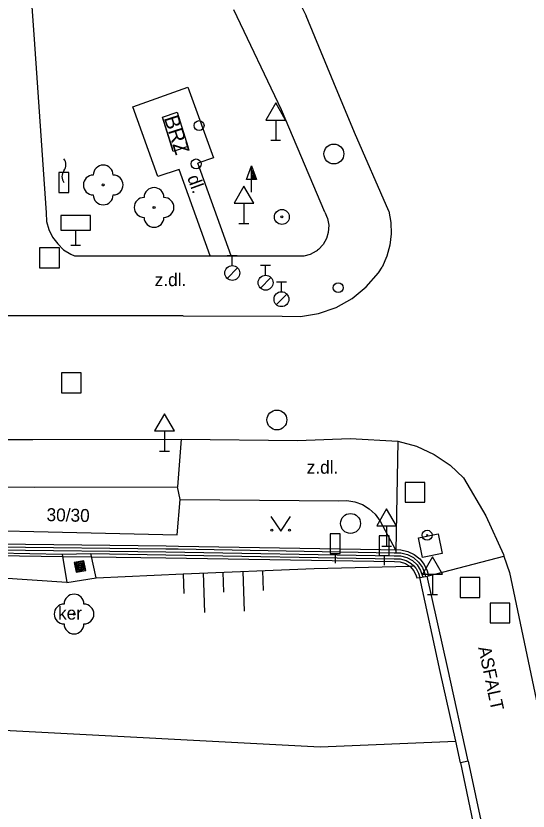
# Model space of a CAD drawing. Extents: x -538441 to -536770, y -1181008 to -1179809.
# Drawn here: x -537827.88 to -537802.07, y -1180541.89 to -1180501.86 of the extents above; entities that cross this region are included whole.
import ezdxf

# ---------------------------------------------------------------- set-up
doc = ezdxf.new("R2010")
doc.units = 0
for name, color, linetype in [('Vrstva 10', 7, 'Continuous'), ('Vrstva 11', 7, 'Continuous'), ('Vrstva 14', 7, 'Continuous'), ('Vrstva 15', 7, 'Continuous'), ('Vrstva 21', 7, 'Continuous'), ('Vrstva 22', 7, 'Continuous'), ('Vrstva 24', 7, 'Continuous'), ('Vrstva 25', 7, 'Continuous'), ('Vrstva 26', 7, 'Continuous'), ('Vrstva 27', 7, 'Continuous'), ('Vrstva 28', 7, 'Continuous'), ('Vrstva 31', 7, 'Continuous'), ('Vrstva 34', 7, 'Continuous'), ('Vrstva 36', 7, 'Continuous'), ('Vrstva 38', 7, 'Continuous'), ('Vrstva 40', 7, 'Continuous'), ('Vrstva 41', 7, 'Continuous'), ('Vrstva 5', 7, 'Continuous'), ('Vrstva 57', 7, 'Continuous'), ('Vrstva 6', 7, 'Continuous'), ('Vrstva 7', 7, 'Continuous'), ('Vrstva 9', 7, 'Continuous')]:
    doc.layers.add(name, color=color, linetype=linetype)

msp = doc.modelspace()

# ---------------------------------------------------------------- linework, layer by layer
at = {"layer": 'Vrstva 10'}
for p, q in [((-537809.09, -1180511.69), (-537810.82, -1180507.735)), ((-537819.46, -1180516.95), (-537839.53, -1180516.98)), ((-537819.46, -1180516.95), (-537814.47, -1180516.98)), ((-537835.714, -1180523.17), (-537827.03, -1180523.18)), ((-537827.03, -1180523.18), (-537819.56, -1180523.17)), ((-537819.56, -1180523.17), (-537813.69, -1180523.23)), ((-537803.01, -1180529.88), (-537801.459, -1180537.207))]:
    msp.add_line(p, q, dxfattribs=at)
for points in [[(-537815.804, -1180496.755), (-537814.527, -1180499.308), (-537814.265, -1180499.831), (-537813.25, -1180501.86)], [(-537810.82, -1180507.735), (-537811.857, -1180505.228), (-537813.25, -1180501.86)], [(-537809.09, -1180511.69), (-537808.995, -1180512.254), (-537808.979, -1180512.826), (-537809.043, -1180513.394), (-537809.185, -1180513.948), (-537809.42, -1180514.51)], [(-537814.47, -1180516.98), (-537813.544, -1180516.988), (-537812.629, -1180516.838), (-537811.75, -1180516.53), (-537810.945, -1180516.081), (-537810.226, -1180515.497), (-537809.617, -1180514.799), (-537809.42, -1180514.51)], [(-537813.69, -1180523.23), (-537811.045, -1180523.141), (-537808.63, -1180523.27)], [(-537808.63, -1180523.27), (-537807.692, -1180523.525), (-537806.808, -1180523.931), (-537806.003, -1180524.476), (-537805.32, -1180525.12)], [(-537805.32, -1180525.12), (-537804.203, -1180527.018), (-537803.32, -1180528.97)], [(-537803.32, -1180528.97), (-537803.291, -1180529.055), (-537803.01, -1180529.88)]]:
    msp.add_lwpolyline(points, dxfattribs=at)
at = {"layer": 'Vrstva 11'}
for p, q in [((-537827.67, -1180492.82), (-537826.98, -1180502.8)), ((-537814.496, -1180506.595), (-537816.902, -1180501.549)), ((-537826.98, -1180502.8), (-537826.36, -1180511.78)), ((-537812.31, -1180511.74), (-537814.496, -1180506.595)), ((-537817.03, -1180513.94), (-537818.72, -1180509.28)), ((-537808.63, -1180523.27), (-537808.73, -1180528.78)), ((-537835.7, -1180525.464), (-537826.94, -1180525.59)), ((-537826.94, -1180525.59), (-537819.73, -1180525.56)), ((-537819.6, -1180526.21), (-537811.61, -1180526.27)), ((-537831.949, -1180528.393), (-537820.316, -1180528.534)), ((-537820.316, -1180528.534), (-537819.693, -1180528.545)), ((-537819.693, -1180528.545), (-537808.486, -1180528.736)), ((-537831.953, -1180528.993), (-537825.505, -1180529.071)), ((-537808.73, -1180528.78), (-537808.732, -1180528.884)), ((-537820.324, -1180529.134), (-537808.797, -1180529.332)), ((-537807.683, -1180530.155), (-537807.535, -1180530.128)), ((-537807.24, -1180530.075), (-537807.158, -1180530.06)), ((-537805.09, -1180539.37), (-537805.48, -1180539.457))]:
    msp.add_line(p, q, dxfattribs=at)
for points in [[(-537821.99, -1180506.44), (-537819.21, -1180505.44), (-537817.93, -1180509.01), (-537818.72, -1180509.28)], [(-537818.09, -1180513.94), (-537819.66, -1180509.59), (-537820.73, -1180509.95), (-537821.99, -1180506.44)], [(-537826.36, -1180511.78), (-537826.33, -1180512.203), (-537826.222, -1180512.614), (-537826.039, -1180512.997), (-537825.77, -1180513.34), (-537825.476, -1180513.627), (-537825.116, -1180513.853), (-537824.92, -1180513.94)], [(-537812.31, -1180511.74), (-537812.174, -1180512.057), (-537812.114, -1180512.396), (-537812.14, -1180512.77), (-537812.233, -1180513.07), (-537812.405, -1180513.369), (-537812.641, -1180513.62), (-537812.69, -1180513.66)], [(-537813.7, -1180513.94), (-537813.362, -1180513.935), (-537813.034, -1180513.851), (-537812.735, -1180513.693), (-537812.69, -1180513.66)], [(-537824.92, -1180513.94), (-537818.09, -1180513.94)], [(-537818.09, -1180513.94), (-537817.03, -1180513.94), (-537813.7, -1180513.94)], [(-537819.56, -1180523.17), (-537819.73, -1180525.56)], [(-537843.21, -1180525.31), (-537843.23, -1180527.47), (-537835.65, -1180527.61), (-537819.75, -1180527.99)], [(-537819.6, -1180526.21), (-537819.73, -1180525.56)], [(-537819.75, -1180527.99), (-537819.6, -1180526.21)], [(-537811.61, -1180526.27), (-537811.203, -1180526.254), (-537810.802, -1180526.318), (-537810.42, -1180526.46), (-537810.074, -1180526.673), (-537809.775, -1180526.949), (-537809.53, -1180527.29)], [(-537809.53, -1180527.29), (-537808.754, -1180528.736), (-537808.73, -1180528.78)], [(-537808.486, -1180528.736), (-537808.138, -1180528.818), (-537807.815, -1180528.975), (-537807.536, -1180529.199), (-537807.313, -1180529.479), (-537807.157, -1180529.802), (-537807.093, -1180530.043)], [(-537825.505, -1180529.071), (-537824.081, -1180529.088)], [(-537824.081, -1180529.088), (-537820.324, -1180529.134)], [(-537808.797, -1180529.332), (-537808.514, -1180529.338), (-537808.243, -1180529.423), (-537808.044, -1180529.555), (-537808.007, -1180529.579), (-537807.823, -1180529.795), (-537807.707, -1180530.054), (-537807.683, -1180530.155)], [(-537807.158, -1180530.06), (-537807.093, -1180530.043), (-537803.291, -1180529.055)], [(-537805.48, -1180539.457), (-537805.72, -1180538.375), (-537806.502, -1180534.855), (-537807.535, -1180530.128)], [(-537805.09, -1180539.37), (-537806.125, -1180534.71), (-537807.158, -1180530.06)]]:
    msp.add_lwpolyline(points, dxfattribs=at)
at = {"layer": 'Vrstva 14'}
for p, q in [((-537819.45, -1180529.941), (-537812.85, -1180529.68)), ((-537825.32, -1180530.39), (-537830.036, -1180530.052)), ((-537823.84, -1180530.14), (-537819.45, -1180529.941)), ((-537843.69, -1180537.02), (-537812.55, -1180538.66)), ((-537812.55, -1180538.66), (-537805.72, -1180538.375))]:
    msp.add_line(p, q, dxfattribs=at)
msp.add_lwpolyline([(-537812.85, -1180529.68), (-537808.044, -1180529.555), (-537807.824, -1180529.549)], dxfattribs=at)
at = {"layer": 'Vrstva 15'}
for p, q in [((-537815.454, -1180529.783), (-537815.414, -1180530.782)), ((-537819.45, -1180529.941), (-537819.411, -1180530.94)), ((-537818.451, -1180529.902), (-537818.372, -1180531.9)), ((-537817.452, -1180529.862), (-537817.412, -1180530.861)), ((-537816.453, -1180529.822), (-537816.374, -1180531.821))]:
    msp.add_line(p, q, dxfattribs=at)
at = {"layer": 'Vrstva 21'}
for radius in [0.375, 0.05]:
    msp.add_circle((-537814.48, -1180511.98), radius, dxfattribs=at)
at = {"layer": 'Vrstva 22'}
for centre in [(-537823.48, -1180510.37), (-537820.92, -1180511.5), (-537824.95, -1180531.97)]:
    msp.add_circle(centre, 0.05, dxfattribs=at)
for centre, start, end in [((-537823.48, -1180509.87), 0, 180), ((-537823.98, -1180510.37), 90, 270), ((-537822.98, -1180510.37), 270, 90), ((-537820.92, -1180511), 0, 180), ((-537823.48, -1180510.87), 180, 0), ((-537821.42, -1180511.5), 90, 270), ((-537820.42, -1180511.5), 270, 90), ((-537820.92, -1180512), 180, 0), ((-537824.95, -1180531.47), 0, 180), ((-537825.45, -1180531.97), 90, 270), ((-537824.45, -1180531.97), 270, 90), ((-537824.95, -1180532.47), 180, 0)]:
    msp.add_arc(centre, 0.5, start, end, dxfattribs=at)
at = {"layer": 'Vrstva 24'}
msp.add_lwpolyline([(-537825.21, -1180510.75), (-537825.21, -1180509.75), (-537825.71, -1180509.75), (-537825.71, -1180510.75)], close=True, dxfattribs=at)
for centre, start, end in [((-537825.86, -1180509.35), 323.1301, 36.8699), ((-537825.06, -1180509.95), 143.1301, 216.8699)]:
    msp.add_arc(centre, 0.5, start, end, dxfattribs=at)
at = {"layer": 'Vrstva 25'}
for p, q in [((-537816.262, -1180510.088), (-537816.01, -1180509.414)), ((-537816.01, -1180510.088), (-537816.262, -1180510.088)), ((-537816.01, -1180510.74), (-537816.01, -1180510.09))]:
    msp.add_line(p, q, dxfattribs=at)
for points in [[(-537815.76, -1180510.09), (-537816.01, -1180510.09), (-537816.01, -1180509.414), (-537816.01, -1180509.414)], [(-537815.817, -1180510.05), (-537815.97, -1180510.05), (-537815.97, -1180509.637)], [(-537815.875, -1180510.01), (-537815.93, -1180510.01), (-537815.93, -1180509.861)], [(-537824.849, -1180529.868), (-537824.358, -1180529.775), (-537824.451, -1180529.284), (-537824.942, -1180529.377)], [(-537824.809, -1180529.81), (-537824.416, -1180529.735), (-537824.491, -1180529.342), (-537824.884, -1180529.417)], [(-537824.77, -1180529.752), (-537824.475, -1180529.696), (-537824.531, -1180529.401), (-537824.826, -1180529.457)], [(-537824.73, -1180529.693), (-537824.533, -1180529.656), (-537824.571, -1180529.459), (-537824.767, -1180529.497)], [(-537824.69, -1180529.635), (-537824.592, -1180529.616), (-537824.61, -1180529.518), (-537824.709, -1180529.536)]]:
    msp.add_lwpolyline(points, close=True, dxfattribs=at)
for radius in [0.25, 0.0303]:
    msp.add_circle((-537807.16, -1180528), radius, dxfattribs=at)
at = {"layer": 'Vrstva 26'}
for points in [[(-537826.69, -1180514.54), (-537825.69, -1180514.54), (-537825.69, -1180513.54), (-537826.69, -1180513.54)], [(-537825.59, -1180520.83), (-537824.59, -1180520.83), (-537824.59, -1180519.83), (-537825.59, -1180519.83)], [(-537808.27, -1180526.34), (-537807.27, -1180526.34), (-537807.27, -1180525.34), (-537808.27, -1180525.34)], [(-537805.5, -1180531.13), (-537804.5, -1180531.13), (-537804.5, -1180530.13), (-537805.5, -1180530.13)], [(-537803.99, -1180532.42), (-537802.99, -1180532.42), (-537802.99, -1180531.42), (-537803.99, -1180531.42)]]:
    msp.add_lwpolyline(points, close=True, dxfattribs=at)
at = {"layer": 'Vrstva 27'}
for centre in [(-537811.86, -1180508.81), (-537814.73, -1180522.2), (-537811.02, -1180527.41)]:
    msp.add_circle(centre, 0.5, dxfattribs=at)
at = {"layer": 'Vrstva 28'}
for p, q in [((-537817.23, -1180513.925), (-537816.73, -1180513.925)), ((-537816.98, -1180514.425), (-537816.98, -1180513.925)), ((-537817.238, -1180515.072), (-537816.708, -1180514.542)), ((-537815.55, -1180514.415), (-537815.05, -1180514.415)), ((-537815.3, -1180514.915), (-537815.3, -1180514.415)), ((-537815.558, -1180515.562), (-537815.028, -1180515.032)), ((-537814.75, -1180515.245), (-537814.25, -1180515.245)), ((-537814.5, -1180515.745), (-537814.5, -1180515.245)), ((-537814.758, -1180516.392), (-537814.228, -1180515.862))]:
    msp.add_line(p, q, dxfattribs=at)
for centre, radius in [((-537816.98, -1180514.8), 0.375), ((-537815.3, -1180515.29), 0.375), ((-537811.64, -1180515.54), 0.25), ((-537814.5, -1180516.12), 0.375)]:
    msp.add_circle(centre, radius, dxfattribs=at)
at = {"layer": 'Vrstva 31'}
for centre in [(-537818.65, -1180507.38), (-537818.8, -1180509.31)]:
    msp.add_circle(centre, 0.25, dxfattribs=at)
at = {"layer": 'Vrstva 34'}
for p, q in [((-537814.79, -1180507.102), (-537814.79, -1180508.12)), ((-537815.04, -1180508.12), (-537814.54, -1180508.12)), ((-537816.39, -1180511.292), (-537816.39, -1180512.31)), ((-537816.64, -1180512.31), (-537816.14, -1180512.31)), ((-537824.87, -1180512.65), (-537824.87, -1180513.4)), ((-537825.12, -1180513.4), (-537824.62, -1180513.4)), ((-537820.39, -1180522.752), (-537820.39, -1180523.77)), ((-537820.64, -1180523.77), (-537820.14, -1180523.77)), ((-537809.2, -1180527.532), (-537809.2, -1180528.55)), ((-537809.45, -1180528.55), (-537808.95, -1180528.55)), ((-537806.89, -1180529.962), (-537806.89, -1180530.98)), ((-537807.14, -1180530.98), (-537806.64, -1180530.98))]:
    msp.add_line(p, q, dxfattribs=at)
for points in [[(-537815.29, -1180507.102), (-537814.29, -1180507.102), (-537814.79, -1180506.236)], [(-537816.89, -1180511.292), (-537815.89, -1180511.292), (-537816.39, -1180510.426)], [(-537825.62, -1180512.65), (-537824.12, -1180512.65), (-537824.12, -1180511.9), (-537825.62, -1180511.9)], [(-537820.89, -1180522.752), (-537819.89, -1180522.752), (-537820.39, -1180521.886)], [(-537809.7, -1180527.532), (-537808.7, -1180527.532), (-537809.2, -1180526.666)], [(-537807.39, -1180529.962), (-537806.39, -1180529.962), (-537806.89, -1180529.096)]]:
    msp.add_lwpolyline(points, close=True, dxfattribs=at)
at = {"layer": 'Vrstva 36'}
msp.add_lwpolyline([(-537815.038, -1180527.054), (-537814.538, -1180527.804), (-537814.038, -1180527.054)], dxfattribs=at)
for centre in [(-537814.988, -1180527.754), (-537814.089, -1180527.754)]:
    msp.add_circle(centre, 0.05, dxfattribs=at)
at = {"layer": 'Vrstva 38'}
for p, q in [((-537811.79, -1180528.925), (-537811.79, -1180529.41)), ((-537809.33, -1180529.025), (-537809.33, -1180529.51))]:
    msp.add_line(p, q, dxfattribs=at)
for points in [[(-537812.04, -1180528.925), (-537811.54, -1180528.925), (-537811.54, -1180527.925), (-537812.04, -1180527.925)], [(-537809.58, -1180529.025), (-537809.08, -1180529.025), (-537809.08, -1180528.025), (-537809.58, -1180528.025)]]:
    msp.add_lwpolyline(points, close=True, dxfattribs=at)
at = {"layer": 'Vrstva 5'}
for p, q in [((-537820.5, -1180506.96), (-537819.76, -1180506.71)), ((-537819.95, -1180508.68), (-537820.5, -1180506.96)), ((-537819.76, -1180506.71), (-537819.21, -1180508.43)), ((-537819.21, -1180508.43), (-537819.95, -1180508.68))]:
    msp.add_line(p, q, dxfattribs=at)
at = {"layer": 'Vrstva 57'}
for p, q in [((-537807.6, -1180528.13), (-537806.61, -1180527.93)), ((-537807.4, -1180529.12), (-537807.6, -1180528.13)), ((-537806.61, -1180527.93), (-537806.41, -1180528.92)), ((-537806.41, -1180528.92), (-537807.4, -1180529.12))]:
    msp.add_line(p, q, dxfattribs=at)
at = {"layer": 'Vrstva 6'}
msp.add_line((-537820.475, -1180507.037), (-537819.988, -1180508.561), dxfattribs=at)
at = {"layer": 'Vrstva 7'}
for p, q in [((-537831.95, -1180528.543), (-537820.318, -1180528.684)), ((-537831.952, -1180528.843), (-537825.55, -1180528.95)), ((-537820.322, -1180528.984), (-537808.815, -1180529.183)), ((-537820.318, -1180528.684), (-537819.699, -1180528.695)), ((-537819.699, -1180528.695), (-537808.829, -1180528.883)), ((-537807.535, -1180530.128), (-537807.24, -1180530.075)), ((-537805.09, -1180539.37), (-537791.4, -1180604.319)), ((-537805.48, -1180539.457), (-537803.174, -1180550.395))]:
    msp.add_line(p, q, dxfattribs=at)
for points in [[(-537825.55, -1180528.95), (-537824.11, -1180528.92)], [(-537825.55, -1180528.95), (-537825.32, -1180530.39), (-537823.84, -1180530.14), (-537824.11, -1180528.92)], [(-537824.11, -1180528.92), (-537820.322, -1180528.984)], [(-537808.829, -1180528.883), (-537808.75, -1180528.884), (-537808.732, -1180528.884), (-537808.488, -1180528.887), (-537808.157, -1180528.97), (-537807.855, -1180529.128), (-537807.597, -1180529.352), (-537807.398, -1180529.629), (-537807.27, -1180529.945), (-537807.24, -1180530.075)], [(-537808.815, -1180529.183), (-537808.511, -1180529.187), (-537808.219, -1180529.269), (-537807.958, -1180529.425), (-537807.824, -1180529.549), (-537807.746, -1180529.643), (-537807.721, -1180529.678), (-537807.598, -1180529.908), (-537807.535, -1180530.128)]]:
    msp.add_lwpolyline(points, dxfattribs=at)
at = {"layer": 'Vrstva 9'}
for p, q in [((-537831.951, -1180528.693), (-537820.32, -1180528.834)), ((-537820.32, -1180528.834), (-537808.82, -1180529.033))]:
    msp.add_line(p, q, dxfattribs=at)
msp.add_lwpolyline([(-537808.82, -1180529.033), (-537808.497, -1180529.037), (-537808.185, -1180529.121), (-537807.902, -1180529.278), (-537807.667, -1180529.5), (-537807.494, -1180529.772), (-537807.385, -1180530.111)], dxfattribs=at)

# ---------------------------------------------------------------- texts
at = {"layer": 'Vrstva 21'}
msp.add_text('ker', height=0.65, dxfattribs=at).set_placement((-537825.755, -1180532.25))
at = {"layer": 'Vrstva 40'}
for s, rotation, p in [('dl.', 289.8455, (-537819.257, -1180509.994)), ('30/30', 358.6666, (-537826.342, -1180527.287)), ('ASFALT', 281.9552, (-537804.595, -1180533.66))]:
    msp.add_text(s, height=0.65, rotation=rotation, dxfattribs=at).set_placement(p)
for p in [(-537820.888, -1180515.464), (-537813.23, -1180524.905)]:
    msp.add_text('z.dl.', height=0.65, dxfattribs=at).set_placement(p)
at = {"layer": 'Vrstva 41'}
msp.add_text('BRZ', height=0.75, rotation=287.7423, dxfattribs=at).set_placement((-537820.429, -1180506.998))

doc.saveas('drawing.dxf')
